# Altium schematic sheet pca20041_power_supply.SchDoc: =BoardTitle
size A3; Organization: Nordic Semiconductor; DocumentNumber: 6; SheetNumber: 6; SheetTotal: 6; CompanyName: Nordic Semiconductor
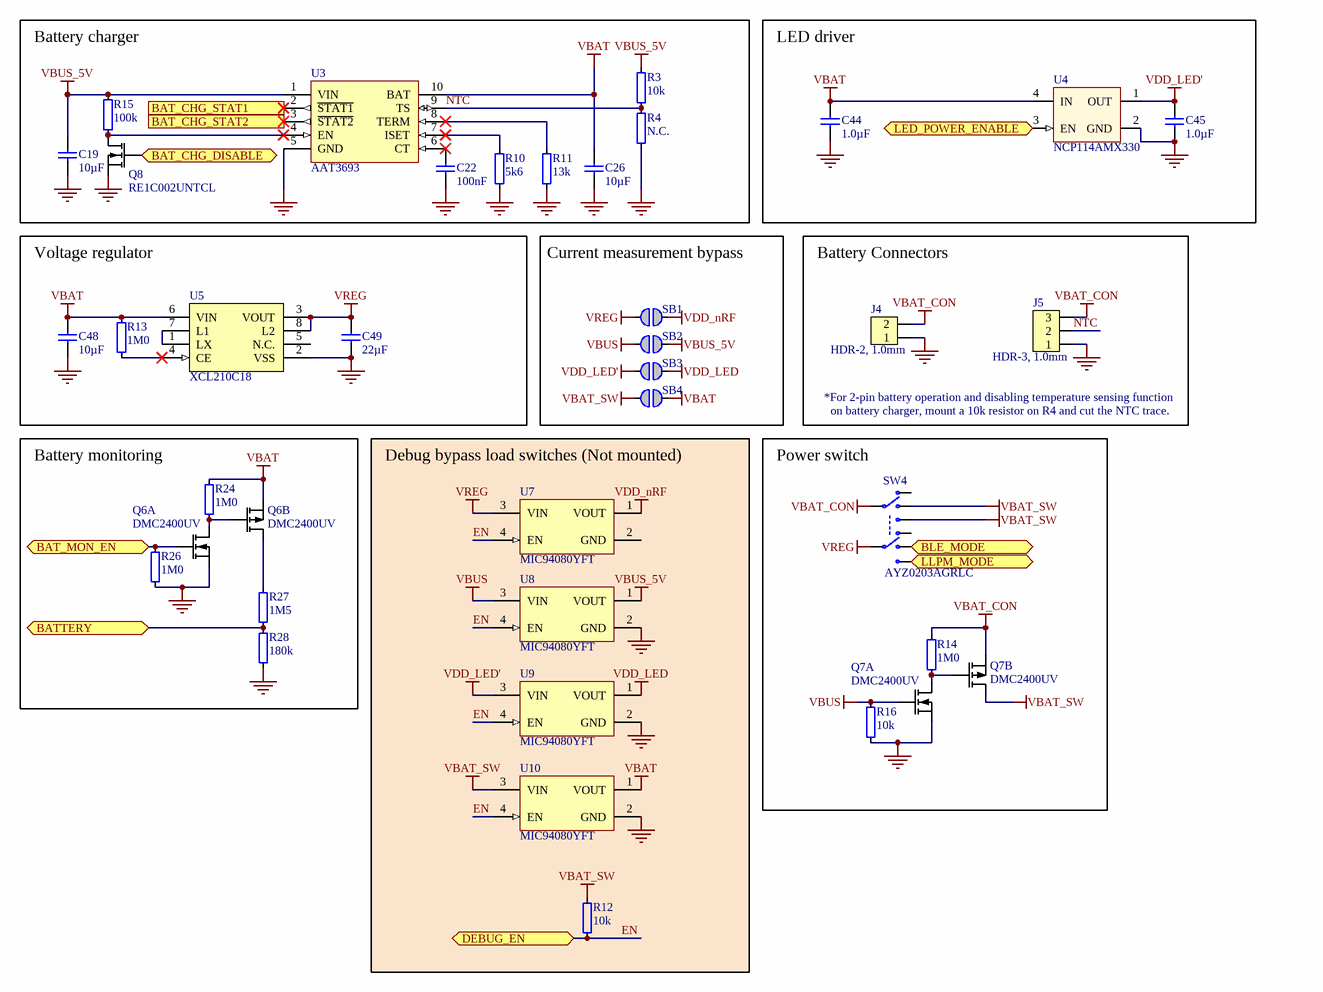
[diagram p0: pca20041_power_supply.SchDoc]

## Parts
C19  10µF  [CAPC1608X06L]
C22  100nF  [CAPC0603X03L_C]
C26  10µF  [CAPC1608X06L]
C44  1.0µF  [CAPC1005X04L]
C45  1.0µF  [CAPC1005X04L]
C48  10µF  [CAPC1608X06L]
C49  22µF  [CAPC1608X06L]
J4  HDR-2, 1.0mm  [BM02B-SRSS-TB]
J5  HDR-3, 1.0mm  [BM03B-SRSS-TB]
Q6  DMC2400UV  [SOTFL50P162X60-6N]  (parts A,B of 2)
Q7  DMC2400UV  [SOTFL50P162X60-6N]  (parts A,B of 2)
Q8  RE1C002UNTCL  [SOTFL50P160X78-3N]
R3  10k  [RESC0603X03L_C]
R4  N.C.  [RESC0603X03L_C_NC]
R10  5k6  [RESC0603X03L_C]
R11  13k  [RESC0603X03L_C]
R12  10k  [RESC1005X04L]
R13  1M0  [RESC1005X04L]
R14  1M0  [RESC0603X03L_C]
R15  100k  [RESC0603X03L_C]
R16  10k  [RESC0603X03L_C]
R24  1M0  [RESC0603X03L_C]
R26  1M0  [RESC0603X03L_C]
R27  1M5  [RESC0603X03L_C]
R28  180k  [RESC0603X03L_C]
SB1  Solderbridge  [Solderbridge]  (value not drawn)  (no BOM)
SB2  Solderbridge  [Solderbridge]  (value not drawn)  (no BOM)
SB3  Solderbridge  [Solderbridge]  (value not drawn)  (no BOM)
SB4  Solderbridge  [Solderbridge]  (value not drawn)  (no BOM)
SW4  AYZ0203AGRLC  [AYZ0203AGRLC]
U3  AAT3693  [QFN40P220X220X80_HS-11N]
U4  NCP114AMX330  [UDFN65P100X100X60_HS-5N]
U5  XCL210C18  [CL-2025]
U7  MIC94080YFT  [TMLF40P85X85X60-4N]
U8  MIC94080YFT  [TMLF40P85X85X60-4N]
U9  MIC94080YFT  [TMLF40P85X85X60-4N]
U10  MIC94080YFT  [TMLF40P85X85X60-4N]

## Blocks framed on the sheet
Battery charger: C19 C22 C26 Q8 R3 R4 R10 R11 R15 U3
LED driver: C44 C45 U4
Voltage regulator: C48 C49 R13 U5
Current measurement bypass: SB1-SB4
Battery Connectors: J4 J5
Battery monitoring: Q6 R24 R26-R28
Debug bypass load switches (Not mounted): R12 U7-U10
Power switch: Q7 R14 R16 SW4

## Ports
BAT_CHG_DISABLE (bidir), BAT_CHG_STAT1 (out), BAT_CHG_STAT2 (out), BAT_MON_EN (bidir), BATTERY (bidir), BLE_MODE (bidir), DEBUG_EN (bidir), LED_POWER_ENABLE (bidir), LLPM_MODE (bidir)

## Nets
GND: C19.1 C22.2 C26.1 C44.2 C45.2 C48.1 C49.1 J4.1 J5.1 Q6.1(S1) Q7.1(S1) Q8.2(S) R4.1 R10.1 R11.1 R16.1 R26.2 R28.2 U3.5(GND) U3.11(GND) U4.2(GND) U4.5(EPAD) U5.2(VSS) U5.9(VSS) U7.2(GND) U8.2(GND) U9.2(GND) U10.2(GND)
VBAT: C26.2 C44.1 C48.2 Q6.4(S2) R13.2 R24.1 SB4.2 U3.10(BAT) U4.4(IN) U5.6(VIN) U10.1(VOUT)
VBAT_CON: J4.2 J5.3 Q7.4(S2) R14.2 SW4.3(COM-1)
VBAT_SW: Q7.3(D2) R12.2 SB4.1 SW4.2(N.O-1) SW4.4(COM-1) U10.3(VIN)
VBUS: Q7.2(G1) R16.2 SB2.1 U8.3(VIN)
VBUS_5V: C19.2 R3.2 R15.2 SB2.2 U3.1(VIN) U8.1(VOUT)
VDD_LED: SB3.2 U9.1(VOUT)
VDD_LED': C45.1 SB3.1 U4.1(OUT) U9.3(VIN)
VDD_nRF: SB1.2 U7.1(VOUT)
VREG: C49.2 SB1.1 SW4.7(COM-2) U5.3(VOUT) U5.8(L2) U7.3(VIN)
BAT_CHG_DISABLE: Q8.1(G) ; port BAT_CHG_DISABLE
BAT_CHG_STAT1: U3.2(~{STAT1}) ; port BAT_CHG_STAT1
BAT_CHG_STAT2: U3.3(~{STAT2}) ; port BAT_CHG_STAT2
BAT_MON_EN: Q6.2(G1) R26.1 ; port BAT_MON_EN
BATTERY: R27.2 R28.1 ; port BATTERY
BLE_MODE: SW4.6(N.O-2) ; port BLE_MODE
EN: R12.1 U7.4(EN) U8.4(EN) U9.4(EN) U10.4(EN) ; port DEBUG_EN
LED_POWER_ENABLE: U4.3(EN) ; port LED_POWER_ENABLE
LLPM_MODE: SW4.8(COM-2) ; port LLPM_MODE
NTC: J5.2 R3.1 R4.2 U3.9(TS)
NetC22_1: C22.1 U3.6(CT)
NetQ6_3: Q6.3(D2) R27.1
NetQ6_5: Q6.5(G2) Q6.6(D1) R24.2
NetQ7_5: Q7.5(G2) Q7.6(D1) R14.1
NetQ8_3: Q8.3(D) R15.1 U3.4(EN)
NetR10_2: R10.2 U3.7(ISET)
NetR11_2: R11.2 U3.8(TERM)
NetR13_1: R13.1 U5.4(CE)
NetU5_1: U5.1(LX) U5.7(L1)

Not connected (* = marked no-connect by the designer): SW4 1(N.C-1) 5(N.C-2); U5 5(N.C.)

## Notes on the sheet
- *For 2-pin battery operation and disabling temperature sensing function
- on battery charger, mount a 10k resistor on R4 and cut the NTC trace.

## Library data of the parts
C19 C26 = C0603-10µF-25V: Capacitor, 0603, 25V, X5R; Part number IPS: N.A.; Artikkelnr Noca: 20039436
C22 = C0201-100n: Capacitor, X5R, ±10%; Part number IPS: 00000001248; Note: 16V; Artikkelnr Noca: N.A.
C44 C45 = C0402-1µ0: Capacitor, X5R, ±5%; Part number IPS: 00000007786; Note: 6.3V; Artikkelnr Noca: 20039235
C48 = C0603-10µ: Capacitor, X5R, ±20%; Part number IPS: 00000007785; Note: 6.3V; Artikkelnr Noca: 20039234
C49 = C0603-22µ-6.3V: CAP CER 22UF 6.3V 20% X5R 0603; Manufacturer: Samsung; Manufacturer Part Number: CL10A226MQ8NRNC; Part number IPS: 00000007787; Artikkelnr Noca: N.A.
J4 = BM02B-SRSS-TB: 1.0mm pitch top entry SMD wire to board connector; Manufacturer: JST; Note: JST, Header; Artikkelnr Noca: N.A.
J5 = BM03B-SRSS-TB: 1.0mm pitch top entry SMD wire to board connector; Manufacturer: JST; Note: JST, Header; Artikkelnr Noca: N.A.
Q6 Q7 = DMC2400UV: Dual N & P Ch MOFET, 1.03A/0.7A, 480mOhm, 450mW; Manufacturer: Diodes Incorporated; Part number IPS: 00000007803; Note: Dual N & P Channel Digital FET; Artikkelnr Noca: N.A.
Q8 = RE1C002UNTCL: MOSFET N-CH 20V 0.2A EMT3; Manufacturer: Rohm Semiconductor; Artikkelnr Noca: N.A.
R3 R16 = R0201-10k: Resistor, ±1%, 0.05W; Part number IPS: 00000001255; Note: Chip Res 1%; Artikkelnr Noca: N.A.
R4 = R0201-N.C.: Not mounted; Assembly: Not mounted; Note: Chip Res; Artikkelnr Noca: N.A.
R10 = R0201-5k6: Resistor, ±1%, 0.05W; Note: Chip Res 1%; Artikkelnr Noca: N.A.
R11 = R0201-13k: Resistor, ±1%, 0.05W; Note: Chip Res 1%; Artikkelnr Noca: N.A.
R12 = R0402-10k: Not Mounted; Part number IPS: 00000002093; Assembly: Not Mounted; Note: Chip Res 1%; Artikkelnr Noca: 27049097
R13 = R0402-1M0: Resistor, ±1%, 0.063W; Part number IPS: 00000006807; Note: Chip Res 1%; Artikkelnr Noca: 27049145
R14 R24 R26 = R0201-1M0: Resistor, ±1%, 0.05W; Note: Chip Res 1%; Artikkelnr Noca: N.A.
R15 = R0201-100k: Resistor, ±1%, 0.05W; Part number IPS: 00000001419; Note: Chip Res 1%; Artikkelnr Noca: N.A.
R27 = R0201-1M5: Resistor, ±1%, 0.05W; Note: Chip Res 1%; Artikkelnr Noca: N.A.
R28 = R0201-180k: Resistor, ±1%, 0.05W; Note: Chip Res 1%; Artikkelnr Noca: N.A.
SB1-SB4 = Solderbridge: Artikkelnr Noca: N.A.
SW4 = AYZ0203AGRLC: Slide Switch DP3T Surface Mount, 100mA, 12V; Manufacturer: C&K Components; Artikkelnr Noca: N.A.
U3 = AAT3693: 1.6 A Single-cell Li-Ion/Polymer Battery Charger; Manufacturer: Skyworks; Manufacturer Part Number: AAT3693IDH-AA-T1; Artikkelnr Noca: N.A.
U4 = NCP114AMX330TBG: 300 mA CMOS Low Dropout Regulator; Manufacturer: ON Semiconductor; Artikkelnr Noca: N.A.
U5 = XCL210C18: 1.8V 200MA INDUCTOR BUILT-IN PFM STEP; Manufacturer: Torex Semiconductor; Manufacturer Part Number: XCL210C181GR-G; Artikkelnr Noca: N.A.
U7-U10 = MIC94080YFT: Not Mounted; Manufacturer: Microchip; Assembly: Not Mounted; Artikkelnr Noca: N.A.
